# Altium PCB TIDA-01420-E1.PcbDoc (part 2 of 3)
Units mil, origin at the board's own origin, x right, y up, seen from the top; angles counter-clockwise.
Board outline 6575 x 7007.88 mil, 4 copper layers (Top Layer, GND, PWR, Bottom Layer), stack 79.834 mil thick; 326 components, 128 nets, 736 pads, 186 vias.
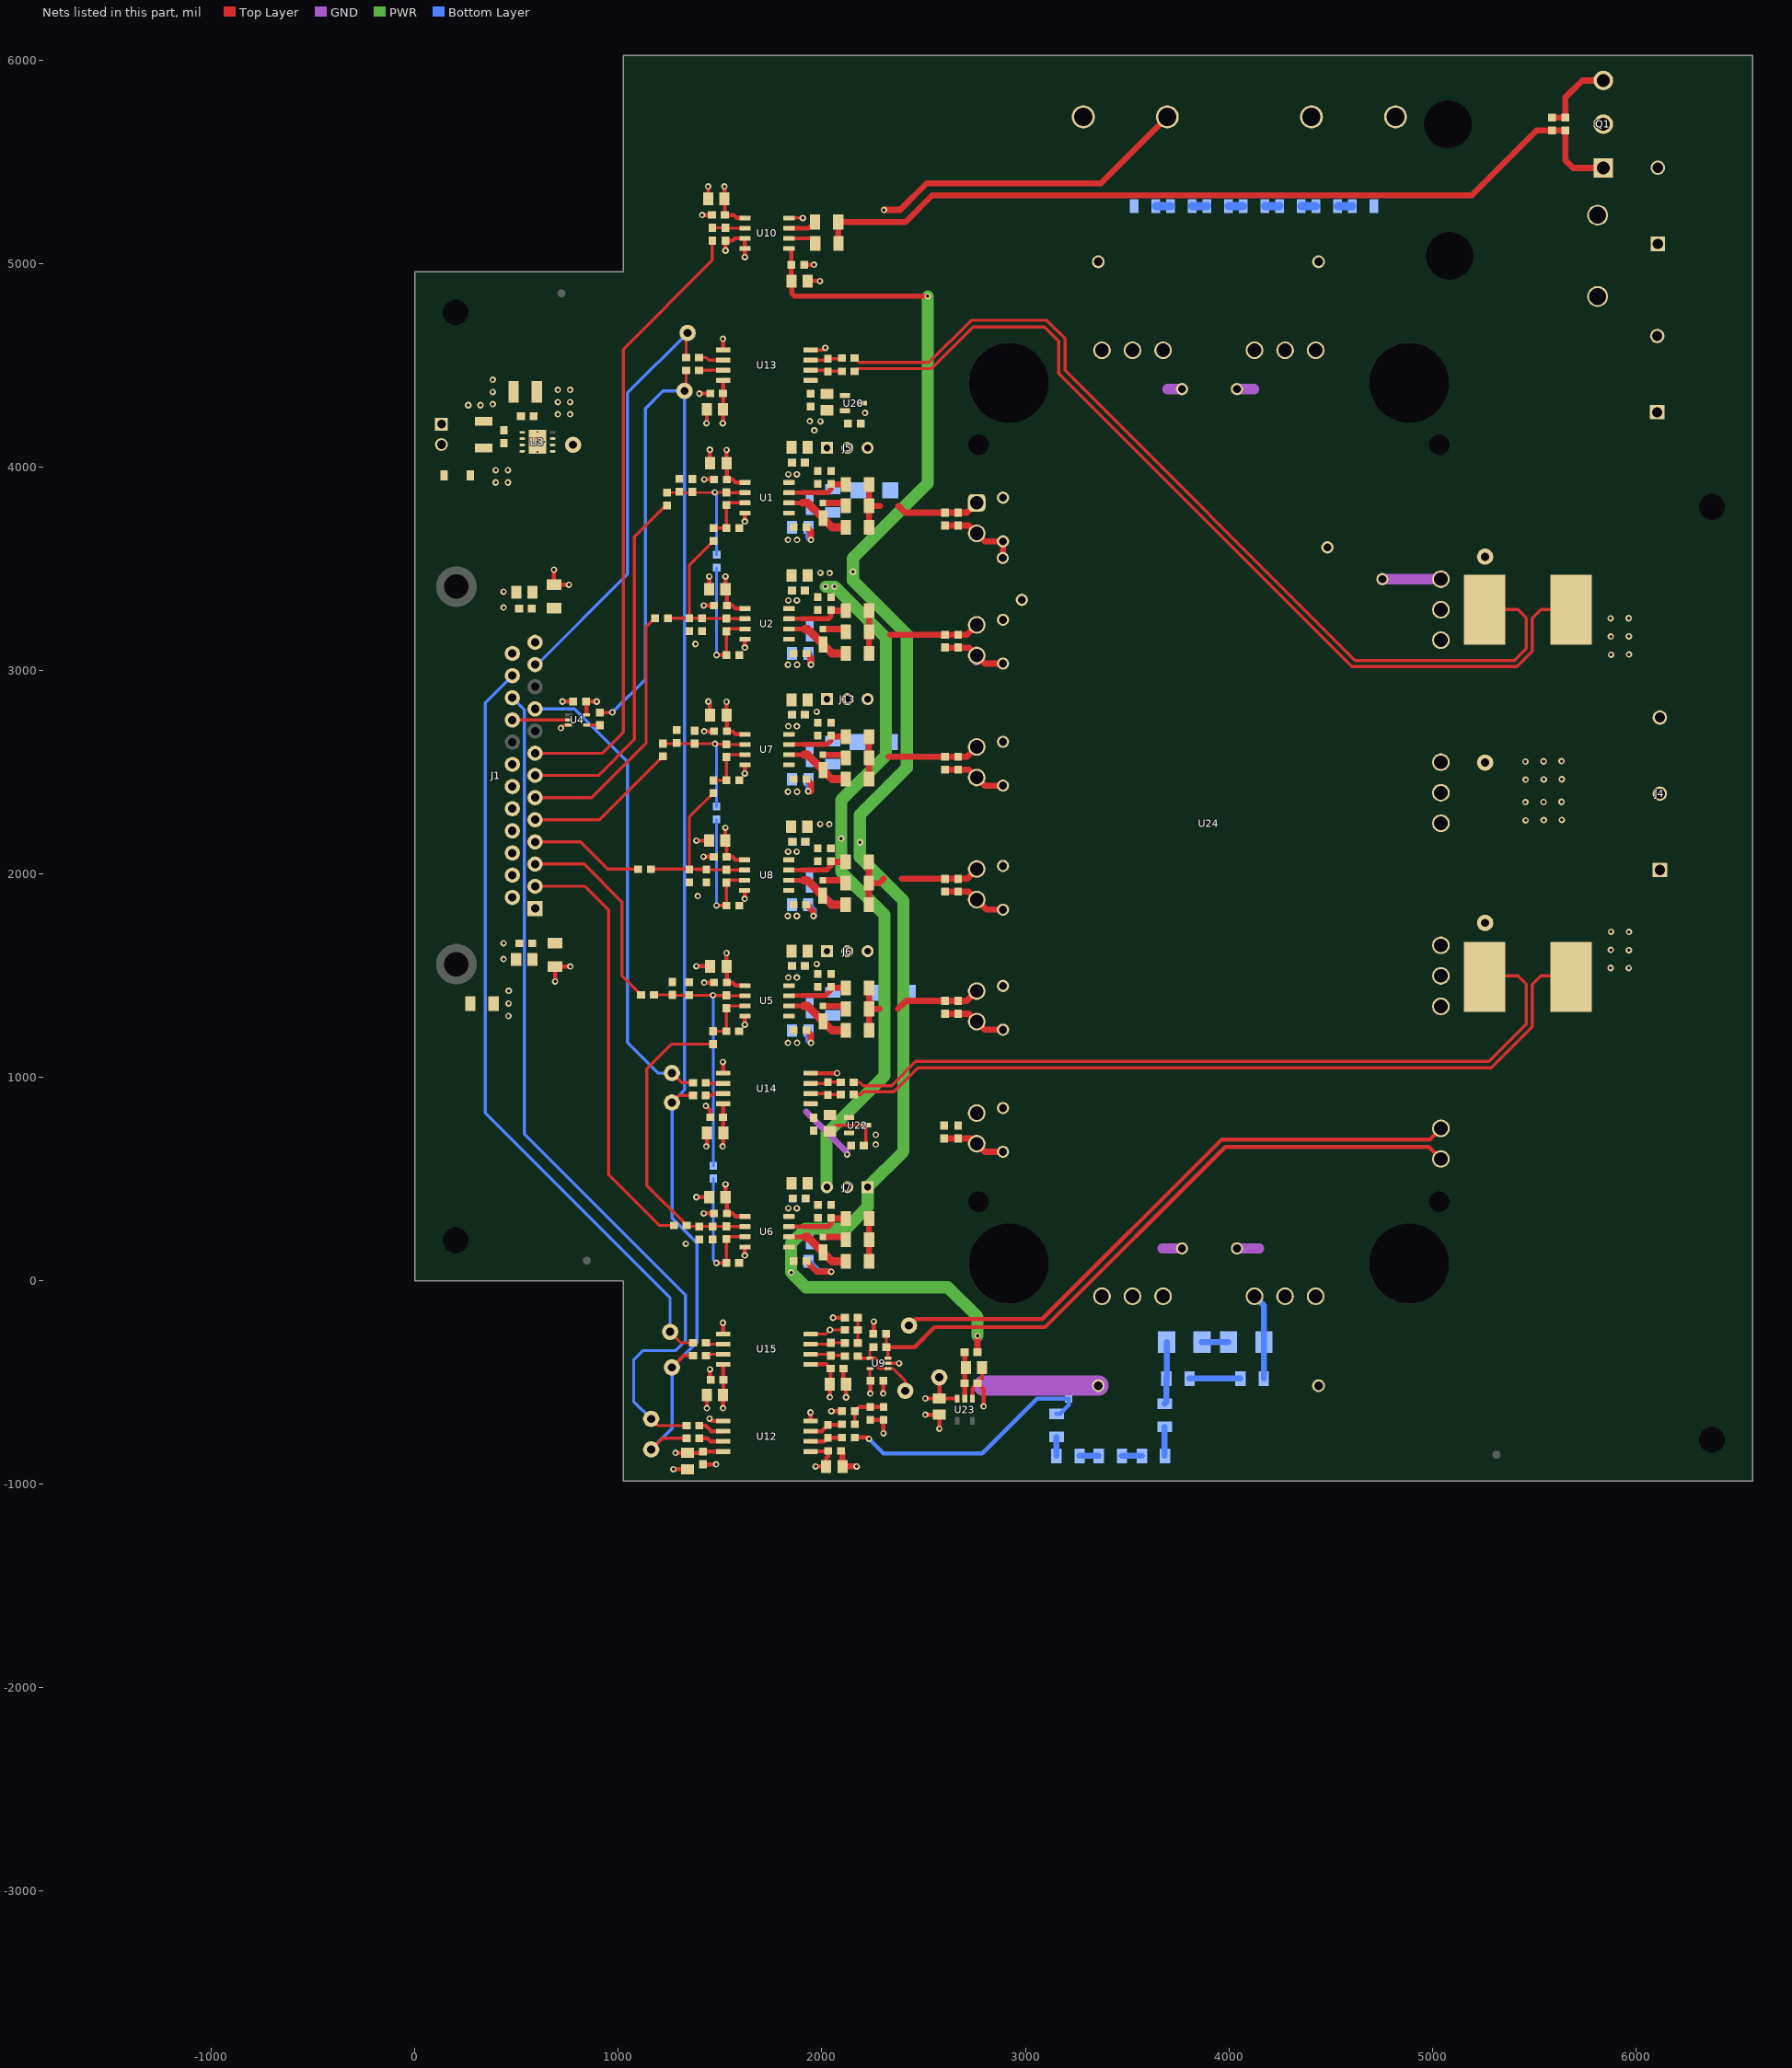
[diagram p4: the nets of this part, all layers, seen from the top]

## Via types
v1: diameter 32, hole 16, Top Layer to Bottom Layer, 181 vias
v2: diameter 19.68, hole 7.87, Top Layer to Bottom Layer, 5 vias

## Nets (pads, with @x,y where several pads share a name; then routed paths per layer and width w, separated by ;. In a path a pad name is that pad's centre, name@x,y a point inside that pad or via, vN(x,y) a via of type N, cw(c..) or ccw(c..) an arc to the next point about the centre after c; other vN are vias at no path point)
3V3: C6.1 C9.1 C11.1 C17.1 C19.1 C22.1 C24.1 C25.1 C27.1 C29.1 C30.1 C36.1 C38.1 C42.1 C44.1 C57.1 C58.2 C59.2 C61.2 C62.2 C63.2 C65.2 C66.2 C68.1 C70.2 TP4.1 U1.1 U2.1 U3.5 U3.6 U3.7 U3.9 U4.5 U5.1 U6.1 U7.1 U8.1 U10.1 U12.8 U13.8 U14.8 U15.8 | length 2691.7
  Top Layer w20: U4.5@843.29,2783.59 843.29,2845.2 C30.1@840.5,2848 v1(893,2848) ; v1(1280,-845) C58.2@1340,-845 1408.5,-845 C63.2@1415,-838.5 C63.2@1415,-838.5 U12.8@1515.17,-838.55 ; v1(1512.73,4216.45) 1514.73,4218.45 C59.2@1514.73,4284.45 1514.73,4361.95 C65.2@1514.23,4362.45 1515.17,4363.39 U13.8@1515.17,4426.58 ; v1@1514.16,663.13 1515.5,664.47 C62.2@1515.5,728 ; C62.2@1514.16,728 1514.16,795.55 1514.94,796.33 U14.8@1514.94,871 ; v1(1514.73,-625.55) C61.2@1514.73,-560.55 1516.23,-559.05 C70.2@1516.23,-485.55 1515.17,-484.49 U15.8@1515.17,-410.55 ; v1(1521.3,5380) C22.1@1521.3,5320 1522.8,5318.5 C11.1@1522.8,5240 1566.3,5240 1581.3,5225 U10.1@1621.73,5225 ; C44.1@1525.3,2165 v1(1525.3,2227.99) ; C29.1@1526.3,412 v1(1526.3,474.99) ; C9.1@1526.3,3400 v1(1526.3,3462.99) ; C44.1@1530.3,2165 1530.3,2160 1531.8,2158.5 C42.1@1531.8,2085 1560.3,2085 1575.3,2070 U8.1@1620.73,2070 ; C29.1@1531.3,412 1531.3,407 1532.8,405.5 C27.1@1532.8,332 1561.3,332 1576.3,317 U6.1@1621.73,317 ; C19.1@1531.3,1541.97 C19.1@1531.3,1546.97 ; v1(1531.3,1611.97) C19.1@1531.3,1546.97 ; C38.1@1531.3,2776.97 C38.1@1531.3,2781.97 ; v1(1531.3,2846.97) C38.1@1531.3,2781.97 ; C9.1@1531.3,3400 1531.3,3395 1532.8,3393.5 C6.1@1532.8,3320 1561.3,3320 1576.3,3305 U2.1@1621.73,3305 ; C57.1@1531.3,4015 C57.1@1531.3,4020 ; v1(1531.3,4085) C57.1@1531.3,4020 ; U5.1@1621.73,1451.97 1576.3,1451.97 1561.3,1466.97 C17.1@1532.8,1466.97 1532.8,1545.47 C19.1@1531.3,1546.97 ; U7.1@1621.73,2686.97 1576.3,2686.97 1561.3,2701.97 C36.1@1532.8,2701.97 1532.8,2780.47 C38.1@1531.3,2781.97 ; U1.1@1621.73,3925 1576.3,3925 1561.3,3940 C68.1@1532.8,3940 1532.8,4018.5 C57.1@1531.3,4020
  other v1: 1512.16,661.13 702,4260 762,4260 702,4320 762,4320 702,4380 762,4380
  other v2: 602,4075.79 568.54,4125 602,4125 635.46,4125 602,4174.21
3V3_VDC: C64.2 C67.2 C79.1 C82.2 C91.2 C95.1 R81.1 R90.2 R106.1 TP7.1 U9.5 U12.1 U15.1 U23.3 | length 1005.6
  Top Layer w15: C79.1@2235.71,-487.2 U9.5@2235.71,-430.59
  Top Layer w20: U12.1@1944.3,-838.55 1945.12,-837.73 2010.42,-837.73 ; U15.1@1944.3,-410.55 1945.12,-409.73 2022.42,-409.73 C91.2@2043.24,-430.55 2043.24,-503.76 C67.2@2039,-508 v1(2039,-571) ; v1(1969,-912) C64.2@2021,-912 2021,-871 2030.77,-861.23 C82.2@2030.77,-835.95 ; v1(2046.5,-639.99) 2047,-639.5 R81.1@2098.5,-639.5 ; v1(2054.73,-180.55) R90.2@2113.24,-180.55 ; C79.1@2235.71,-487.2 C79.1@2238.5,-490 v1(2238.5,-553) ; R106.1@2255.27,-257.95 v1(2255.27,-199.45) ; v1(2508.33,-577.68) C95.1@2577.33,-577.68 ; TP7.1@2577,-474 2577.33,-474.33 C95.1@2577.33,-577.68 ; TP7.1@2577.33,-460.95 TP7.1@2579.73,-458.55 ; U23.3@2664.93,-578.55 2664.06,-577.68 C95.1@2577.33,-577.68
5V0: C5.1 C14.1 D1.1 R1.1 R6.1 U3.2 U3.3 U3.4 | length 296.1
  Top Layer w20: R6.1@683,3422.09 756.91,3422.09 v1(757,3422.17) ; v1(683,3496.17) 683.09,3496.09 R6.1@683.09,3422.17 ; R1.1@688.91,1546 688.91,1472.09 v1(689,1472) ; R1.1@689,1545.91 762.91,1545.91 v1(763,1546)
  other v1: 397,3925 457,3925 397,3985 457,3985
BRAKE_IGBT_GATE: C78.1 Q1.1 R71.2 R94.2 R96.2 | length 4214
  Top Layer w30: R94.2@2080.44,5099.25 R71.2@2080.44,5205.25 2411.25,5205.25 2542,5336 5193.99,5336 5513,5655.01 R96.2@5589,5655.01 C78.1@5654,5655.01 5654,5510 5693,5471 Q1.1@5841,5471
GND: C1.1 C2.1 C5.2 C6.2 C7.2 C8.2 C9.2 C10.2 C11.2 C14.2 C17.2 C19.2 C22.2 C24.2 C25.2 C27.2 C29.2 C30.2 C36.2 C38.2 C42.2 C44.2 C57.2 C58.1 C59.1 C61.1 C62.1 C63.1 C65.1 C66.1 C68.2 C70.1 C162.2 C163.2 C164.2 C165.2 C166.2 C167.2 J1.14 J1.15 J1.16 J1.17 J1.18 J1.19 J1.20 J1.25 J2.1 R44.1 R162.1 R163.1 R164.1 R165.1 R166.1 R167.1 R168.1 R169.1 R170.1 R171.1 R172.1 R173.1 U1.4 U2.4 U3.1 U4.3 U5.4 U6.4 U7.4 U8.4 U10.3 U10.4 U12.5 U13.5 U14.5 U15.5 | length 2149.5
  Top Layer w15: v1(717,2718) 731.41,2732.41 U4.3@754.71,2732.41
  Top Layer w20: v1@460,1364 v1(460.09,1364.09) ; v1(725,2848) C30.2@777.5,2848 ; v1(1270,-925) 1279.72,-925 C58.1@1340,-925 ; v1(1383.31,412) C29.2@1446.3,412 ; v1(1383.31,1546.97) C19.2@1449.8,1546.97 ; v1(1383.31,2164) C44.2@1446.3,2164 ; v1(1397.73,4361.45) 1398.73,4362.45 C65.1@1451.24,4362.45 ; v1@1409.29,5240 v1(1411.3,5240) C11.2@1459.8,5240 ; C63.1@1414.05,-900.27 1415.55,-901.76 v1(1480.55,-901.76) ; v1(1418.29,2085) C42.2@1468.8,2085 ; v1(1419.29,332) C27.2@1469.8,332 ; v1@1419.29,1466.97 v1(1421.3,1466.97) C17.2@1469.8,1466.97 ; v1@1419.29,2701.97 v1(1421.3,2701.97) C36.2@1469.8,2701.97 ; v1(1419.29,3320) C6.2@1469.8,3320 ; v1@1419.29,3940 v1(1421.3,3940) C68.2@1469.8,3940 ; v1(1429.77,860.55) 1451.01,839.31 C66.1@1451.01,804 ; v1(1432.73,4216.45) 1434.73,4218.45 C59.1@1434.73,4284.45 ; v1@1434.16,663.13 1435.5,664.47 C62.1@1435.5,728 ; C62.1@1434.16,728 C62.1@1434.16,729.13 ; v1(1434.73,-625.55) C61.1@1434.73,-560.55 C61.1@1436.23,-559.05 ; C22.2@1441.3,5320 v1(1441.3,5380) ; v1(1442.3,2848) v1@1445.26,2848 ; C9.2@1446.3,3400 v1(1446.3,3462.99) ; v1(1448,-677) 1459.55,-688.55 U12.5@1515.17,-688.55 ; v1(1449.3,4086) 1449.8,4086.5 C57.2@1449.8,4020 ; C38.2@1449.8,2781.97 v1@1449.8,2848.47 ; v1(1450,-435) 1450,-482.31 C70.1@1453.24,-485.55 C70.1@1454.73,-487.05 ; v1(1513.09,1076.25) 1514.59,1074.76 U14.5@1514.59,1021.25 ; v1(1513.67,-205.55) 1515.17,-207.05 U15.5@1515.17,-260.55 ; v1(1513.67,4631.58) 1515.17,4630.08 U13.5@1515.17,4576.58 ; v1@1526.3,5062.99 v1(1526.3,5065) C10.2@1526.3,5113.5 1559.8,5113.5 1571.3,5125 U10.3@1621.73,5125 U10.4@1621.73,5075 1621.73,5033.46 v1(1621.3,5033.03) ; v1(1620.3,1878.03) 1620.73,1878.46 U8.4@1620.73,1920 ; v1(1621.3,125.03) 1621.73,125.46 U6.4@1621.73,167 ; v1(1621.3,1260) 1621.73,1260.43 U5.4@1621.73,1301.97 ; v1(1621.3,2495) 1621.73,2495.43 U7.4@1621.73,2536.97 ; v1(1621.3,3113.03) 1621.73,3113.46 U2.4@1621.73,3155 ; v1(1621.3,3733.03) 1621.73,3733.46 U1.4@1621.73,3775
  other v1: 1331,183 1432.16,661.13 459.17,1302.17 461,1426 435,1582 435,1660 1390,1892 1379,3131 435,3310 435,3388 262,4305 322,4305 382.77,4309.98 382.77,4369.98 382.77,4429.98
GND_UT: C18.1 C20.1 C21.1 C23.2 C26.2 C74.2 C85.1 C89.1 J6.2 R14.2 R16.2 R112.1 TP18.1 U14.4 U22.3 U24.10 | length 863.2
  Top Layer w15: C85.1@2039.77,735.55 2069.77,765.55 U22.3@2216.11,765.55 C21.1@2216.11,675.39
  Top Layer w20: U14.4@1944.07,1021 2074.22,1021 v1(2074.77,1021.55)
  Top Layer w30: C23.2@1924.5,1231.97 1946,1210.47 v1@1946,1170.97 ; R112.1@2605,1313.5 C74.2@2670,1313.5 2722.2,1313.5 U24.10@2761.14,1274.57 2800.71,1235 TP18.1@2890,1235
  Bottom Layer w30: C26.2@1934,1230.97 1934,1181.97 v1(1946,1169.97)
  other v1: 2264.77,670.55 2264.77,718.55 1975,1558
GND_VT: C37.1 C39.1 C40.2 C41.2 C73.2 J13.2 R28.2 R30.2 R32.1 TP16.1 U24.6 | length 446.8
  Top Layer w30: C40.2@1924.5,2466.97 1946,2445.47 v1@1946,2405.97 ; R32.1@2605,2513.5 C73.2@2670,2513.5 2722.2,2513.5 U24.6@2761.14,2474.57 2800.71,2435 TP16.1@2890,2435
  Bottom Layer w30: v1(1933,2407) 1933,2415.97 1934,2416.97 C41.2@1934,2465.97
  other v1: 1975,2798
GND_WT: C3.2 C4.2 C15.1 C16.1 C71.1 C72.2 C80.1 C87.1 J5.2 R2.2 R4.2 R20.1 TP13.1 TP30.1 U13.4 U20.3 U24.2 | length 611.8
  Top Layer w15: U13.4@1944.3,4576.58 2006.58,4576.58 v1(2017,4587)
  Top Layer w30: C3.2@1924.5,3705 1946,3683.5 v1@1946,3644 ; R20.1@2605,3713.5 C72.2@2670,3713.5 2722.2,3713.5 U24.2@2761.14,3674.57 2800.71,3635 TP13.1@2890,3635 2890,3555 TP30.1@2889,3554
  Bottom Layer w30: C4.2@1934,3704 1934,3655 v1(1946,3643)
  other v1: 1963,4181 1993,4225 1941,4226 2212,4267
IN+_B_U: C105.1 C163.1 R144.1 R151.1 R163.2 U6.2 | length 1512.9
  Top Layer w15: R144.1@1335.5,268.5 C105.1@1531.3,268.5 1532.8,267 U6.2@1621.73,267 ; R144.1@1335.5,273 1140,468.5 1140,1042 1262.5,1164.5 R151.1@1465.37,1164.5
IN+_B_V: C103.1 C167.1 R141.1 R159.1 R167.2 U8.2 | length 937.6
  Top Layer w15: R141.1@1159.32,2024.1 R167.2@1348.37,2024.1 ; R167.2@1348.82,2022.59 1348.37,2023.05 R167.2@1348.37,2024.1 ; 1381.87,2021.5 C103.1@1530.3,2021.5 1531.8,2020 U8.2@1620.73,2020 ; C167.1@1432.82,2022.58 1431.31,2024.1 R167.2@1348.37,2024.1 ; R159.1@1466.37,2397.5 1348.37,2279.5 R167.2@1348.37,2024.1
IN+_B_W: C101.1 C165.1 R139.1 R155.1 R165.2 U2.2 | length 807.5
  Top Layer w15: R139.1@1243.5,3257 1243.8,3257.31 R165.2@1348.3,3257.31 ; 1386.69,3257.31 R165.2@1348.3,3257.31 ; 1387.5,3256.5 C101.1@1531.3,3256.5 1532.8,3255 U2.2@1621.73,3255 ; R155.1@1467,3637.5 1349,3519.5 1349,3258.01 R165.2@1348.3,3257.31
IN+_T_U: C106.1 C162.1 R143.1 R150.2 R162.2 U5.2 | length 1292.6
  Top Layer w15: R143.1@1174.5,1406 1175,1406.5 C162.1@1265,1406.5 1267.5,1404 v1(1465,1404) ; v1@1472,1405 1467.83,1405 1466.3,1403.47 C106.1@1531.3,1403.47 1532.8,1401.97 U5.2@1621.73,1401.97
  Bottom Layer w15: R150.2@1466,566.5 v1@1466,1399 ; v1@1472,1399 v1@1472,1405
IN+_T_V: C104.1 C166.1 R142.1 R158.1 R166.2 U7.2 | length 722.4
  Top Layer w15: R142.1@1219,2641.5 v1@1471.97,2641.5 ; v1@1466.3,2638.47 C104.1@1531.3,2638.47 1532.8,2636.97 U7.2@1621.73,2636.97
  Bottom Layer w15: v1(1475,2641) 1482,2634 R158.1@1482,2332.5 R158.1@1482,2330.5
IN+_T_W: C102.1 C164.1 R140.1 R154.1 R164.2 U1.2 | length 700.4
  Top Layer w12: R140.1@1239,3874.5 v1@1472,3874.5
  Top Layer w15: v1@1466.3,3876.5 v1(1474,3876.5) C102.1@1531.3,3876.5 1532.8,3875 U1.2@1621.73,3875
  Bottom Layer w12: v1(1474,3876.5) v1@1482,3868.5
  Bottom Layer w15: R154.1@1482,3568.5 v1@1482,3868.5
IN-_B_U: C105.2 R150.1 R169.2 U6.3 | length 682.8
  Top Layer w15: v1(1481.5,88.5) R169.2@1530.3,88.5 1530.3,204.5 C105.2@1531.3,205.5 1542.8,217 U6.3@1621.73,217
  Bottom Layer w15: R150.1@1466,503.5 1466,104 v1(1481.5,88.5)
IN-_B_V: C103.2 R158.2 R173.2 U8.3 | length 679.3
  Top Layer w15: v1(1482.2,1845.5) R173.2@1531,1845.5 1531,1957.8 C103.2@1530.3,1958.5 1541.8,1970 U8.3@1620.73,1970
  Bottom Layer w15: v1(1482.2,1845.5) R158.2@1482.2,2267.5
IN-_B_W: C101.2 R154.2 R171.2 U2.3 | length 690.2
  Top Layer w15: v1(1482.2,3076.5) R171.2@1531,3076.5 1531,3193.2 C101.2@1531.3,3193.5 1542.8,3205 U2.3@1621.73,3205
  Bottom Layer w15: R154.2@1482,3505.5 1482.2,3505.3 v1(1482.2,3076.5)
IN-_T_U: C106.2 R151.2 R168.2 U5.3 | length 273.5
  Top Layer w15: R151.2@1465.37,1227.5 R168.2@1530.3,1227.5 1530.3,1339.47 C106.2@1531.3,1340.47 1542.8,1351.97 U5.3@1621.73,1351.97
IN-_T_V: C104.2 R159.2 R172.2 U7.3 | length 274.9
  Top Layer w15: R159.2@1466.37,2460.5 1531,2460.5 R172.2@1531.3,2460.8 C104.2@1531.3,2575.47 1542.8,2586.97 U7.3@1621.73,2586.97
IN-_T_W: C102.2 R155.2 R170.2 U1.3 | length 272.3
  Top Layer w15: R155.2@1467,3700.5 R170.2@1531,3700.5 1531.3,3700.8 C102.2@1531.3,3813.5 1542.8,3825 U1.3@1621.73,3825
MCLK: R7.2 R46.2 R52.2 R55.2 R58.2 TP2.1 TP6.1 TP11.1 TP15.1 | length 7770.9
  Top Layer w15: v1@969.5,2794.5 v1(970,2795) ; TP6.1@1325,4375 1333.01,4383.01 R52.2@1333.01,4476
  Top Layer w16: R7.2@909,2794.5 v1@969.5,2794.5 ; TP2.1@1161,-828 1216,-773 R55.2@1335.01,-773 ; TP15.1@1263,-425 1321,-367 R58.2@1367.01,-367 ; TP11.1@1263,877 1297.55,911.55 R46.2@1366.46,911.55
  Bottom Layer w16: v1(970,2795) 1132,2957 1132,4288 1219,4375 TP6.1@1325,4375 1325,939 TP11.1@1263,877 1263,310 1387,186 1387,-301 TP15.1@1263,-425 1263,-726 TP2.1@1161,-828
MDATA_TMP: J1.24 R59.2 TP3.1 | length 3792.7
  Top Layer w15: TP3.1@1254,-250 1308,-304 R59.2@1367.01,-304
  Bottom Layer w15: J1.24@478.5,2975.5 345,2842 345,826 1254,-83 TP3.1@1254,-250
MDATA_U: J1.10 R47.2 TP10.1 | length 2345.8
  Top Layer w15: TP10.1@1263,1022 1310.45,974.55 R47.2@1366.46,974.55
  Bottom Layer w15: J1.10@590.5,2812 785,2812 1045,2552 1045,1171.32 1194.32,1022 TP10.1@1263,1022
MDATA_VDC: J1.23 R56.2 TP1.1 | length 4323.6
  Top Layer w15: TP1.1@1161,-678 1194,-711 R56.2@1335.01,-711
  Bottom Layer w15: J1.23@478.5,2866.5 537.5,2807.5 537.5,2790.05 538,2789.55 538,2725.45 537.5,2724.95 537.5,2681.05 538,2680.55 538,2616.45 537.5,2615.95 537.5,2572.05 538,2571.55 538,2507.45 537.5,2506.95 537.5,2463.05 538,2462.55 538,2398.45 537.5,2397.95 537.5,2354.05 538,2353.55 538,2289.45 537.5,2288.95 537.5,2245.05 538,2244.55 538,2180.45 537.5,2179.95 537.5,2136.05 538,2135.55 538,2071.45 537.5,2070.95 537.5,2027.05 538,2026.55 538,1962.45 537.5,1961.95 537.5,1918.05 538,1917.55 538,1875.42 537.5,1874.92 537.5,1787.08 538,1786.58 538,722 1330,-70 1330,-294 1282,-342 1122,-342 1075,-389 1075,-592 TP1.1@1161,-678
MDATA_W: J1.12 R53.2 TP5.1 | length 2069.8
  Top Layer w15: R53.2@1333.01,4532 R53.2@1333.01,4539 1333.01,4653.01 TP5.1@1335,4655
  Bottom Layer w15: J1.12@590.5,3030 600,3030 1045,3475 1045,4365 TP5.1@1340,4660
NetC1_2: C1.2 C2.2 J1.1 R1.2
NetC7_1: C7.1 C8.1 J1.13 R6.2
NetC10_1: C10.1 R8.1 U10.2 | length 161.1
  Top Layer w15: R8.1@1461.3,5176.5 C10.1@1526.3,5176.5 1527.8,5175 U10.2@1621.73,5175
NetC12_2: C12.2 C13.2 R10.1 R102.2 U2.8
  other v1: 1835,3345 1877,3345
NetC15_2: C15.2 C16.2 R4.1 R100.2 U1.8
  other v1: 1835,3965 1877,3965
NetC18_2: C18.2 C20.2 R16.1 R99.2 U5.8
  other v1: 1835,1491.97 1877,1491.97
NetC28_2: C28.2 C31.2 R24.1 R101.2 U6.8
  other v1: 1835,357 1877,357
NetC37_2: C37.2 C39.2 R30.1 R103.2 U7.8
  other v1: 1835,2726.97 1877,2726.97
NetC43_2: C43.2 C45.2 R36.1 R105.2 U8.8
  other v1: 1834,2110 1876,2110
NetC80_2: C80.2 C87.2 U13.1 U20.1
NetC81_1: C81.1 R83.2 U12.2 | length 162.1
  Top Layer w20: U12.2@1944.3,-788.55 2012.44,-788.55 C81.1@2030,-770.99 2097.01,-770.99 R83.2@2098.5,-769.5
NetC81_2: C81.2 R82.2 U12.3 | length 167.5
  Top Layer w20: U12.3@1944.3,-738.55 1998.6,-738.55 2003.84,-733.31 C81.2@2029.15,-708 ; C81.2@2030,-708 2095,-708 R82.2@2098.5,-704.5
NetC83_1: C83.1 R86.2 U13.2 | length 157.2
  Top Layer w15: U13.2@1944.3,4476.58 2023.24,4476.58 C83.1@2029.73,4470.08 2031.23,4471.58 R86.2@2098.24,4471.58
NetC83_2: C83.2 R85.2 U13.3 | length 153.1
  Top Layer w15: U13.3@1944.3,4526.58 C83.2@2023.24,4526.58 ; C83.2@2029.73,4533.07 R85.2@2094.73,4533.07
  Top Layer w20: C83.2@2023.24,4526.58 C83.2@2029.73,4533.07
NetC84_1: C84.1 R80.2 U14.2 | length 157.2
  Top Layer w15: U14.2@1943.72,921.25 2022.66,921.25 2029.16,914.76 2030.65,916.25 R80.2@2097.66,916.25
NetC84_2: C84.2 R79.2 U14.3 | length 153.1
  Top Layer w15: U14.3@1943.72,971.25 C84.2@2022.66,971.25 ; C84.2@2029.16,977.75 R79.2@2094.16,977.75
  Top Layer w20: C84.2@2022.66,971.25 C84.2@2029.16,977.75
NetC85_2: C85.2 C89.2 U14.1 U22.1
NetC92_1: C92.1 R93.2 U15.2 | length 172.2
  Top Layer w15: U15.2@1944.3,-360.55 2038.24,-360.55 C92.1@2044.73,-367.05 2046.23,-365.55 R93.2@2113.24,-365.55
NetC92_2: C92.2 R92.2 U15.3 | length 172.2
  Top Layer w15: U15.3@1944.3,-310.55 2038.24,-310.55 C92.2@2044.73,-304.05 2111.74,-304.05 R92.2@2113.24,-305.55
NetC94_2: C94.2 R81.2 R82.1 R107.2 | length 213.8
  Top Layer w15: R82.1@2161.5,-704.5 R81.2@2161.5,-639.5
  Top Layer w20: R81.2@2162.82,-640.82 2183.64,-620 R107.2@2238,-620 C94.2@2303,-620
NetC96_1: C96.1 C97.1 R110.2 U23.2 | length 232.6
  Top Layer w25: R110.2@2701.84,-350.68 2701.84,-421.19 C96.1@2707.33,-426.68 2701.84,-432.18 C97.1@2701.84,-502.68 2702.33,-503.18 U23.2@2702.33,-578.55
NetD1_2: D1.2 J2.2
NetD2_1: D2.1 R13.1 U2.6 | length 313.1
  Top Layer w22: U2.6@1854.57,3205 1917,3205
  Top Layer w40: 1917,3205 1929.41,3205 D2.1@2005,3129.41 2049.41,3085 R13.1@2117.91,3085
NetD2_2: D2.2 R11.1 | length 98.7
  Top Layer w30: D2.2@2005,3204.21 R11.1@2103.7,3204.21
NetD3_1: D3.1 R19.1 U1.6 | length 313.1
  Top Layer w22: U1.6@1854.57,3825 1906,3825
  Top Layer w40: 1906,3825 1929.41,3825 D3.1@2005,3749.41 2049.41,3705 R19.1@2117.91,3705
NetD3_2: D3.2 R17.1 | length 98.7
  Top Layer w30: D3.2@2005,3824.21 R17.1@2103.7,3824.21
NetD4_1: D4.1 R21.1 U5.6 | length 313.1
  Top Layer w22: U5.6@1854.57,1351.97 1912,1351.97
  Top Layer w40: 1912,1351.97 1929.41,1351.97 D4.1@2005,1276.38 2049.41,1231.97 R21.1@2117.91,1231.97
NetD4_2: D4.2 R18.1 | length 118.8
  Top Layer w30: D4.2@2005,1351.18 2103.7,1351.18 R18.1@2117.91,1336.97
NetD5_1: D5.1 R27.1 U6.6 | length 313.1
  Top Layer w22: U6.6@1854.57,217 1917,217
  Top Layer w40: 1917,217 1929.41,217 D5.1@2005,141.41 2049.41,97 R27.1@2117.91,97
NetD5_2: D5.2 R25.1 | length 98.7
  Top Layer w30: D5.2@2005,216.21 R25.1@2103.7,216.21
NetD6_1: D6.1 R33.1 U7.6 | length 313.1
  Top Layer w22: U7.6@1854.57,2586.97 1914,2586.97
  Top Layer w40: 1914,2586.97 1929.41,2586.97 D6.1@2005,2511.38 2049.41,2466.97 R33.1@2117.91,2466.97
NetD6_2: D6.2 R31.1 | length 98.7
  Top Layer w30: D6.2@2005,2586.18 R31.1@2103.7,2586.18
NetD7_1: D7.1 R39.1 U8.6 | length 313.1
  Top Layer w22: U8.6@1853.57,1970 1912,1970
  Top Layer w40: 1912,1970 1928.41,1970 D7.1@2004,1894.41 2048.41,1850 R39.1@2116.91,1850
NetD7_2: D7.2 R37.1 | length 98.7
  Top Layer w30: D7.2@2004,1969.21 R37.1@2102.7,1969.21
NetD9_2: D9.2 J3.1 Q1.2
NetD10_2: D10.2 D11.1 | length 130
  Bottom Layer w30: D11.1@3868.75,-300.55 D10.2@3998.73,-300.55
NetD11_2: D11.2 R108.1 R122.2 | length 306.4
  Bottom Layer w30: R122.2@3685,-602.91 3692.91,-595 R108.1@3692.91,-480 3694.73,-478.18 D11.2@3694.73,-300.55
NetD12_1: D12.1 R41.2
NetD13_1: D13.1 R42.2
NetD14_1: D14.1 R43.2
NetJ1_22: J1.22 U4.2 | length 276.4
  Top Layer w15: J1.22@478.5,2757.5 754.21,2757.5 U4.2@754.71,2758
NETJ1_26: R44.2
NetJ4_2: J4.2 TP31.1 U24.24 U24.25 U24.26
  other v1: 5459,2264 5548,2265 5637,2266 5458,2353 5547,2354 5636,2355 5459,2464 5548,2465 5637,2466 5458,2553 5547,2554 5636,2555
NetR2_1: R2.1 R3.1 U1.7 | length 298.3
  Top Layer w20: U1.7@1854.57,3875 1905,3875
  Top Layer w25: 1905,3875 2028,3875 2045,3892 R2.1@2045,3918.5
  Top Layer w30: R2.1@2045,3918.5 2048.5,3915 R3.1@2117.91,3915
NetR5_1: R5.1 R9.1 U2.7 | length 300.7
  Top Layer w20: U2.7@1854.57,3255 1903,3255
  Top Layer w25: 1903,3255 2003.87,3255 2032,3255 2045,3268 R5.1@2045,3298.5
  Top Layer w30: R5.1@2045,3298.5 2048.5,3295 R9.1@2117.91,3295
NetR7_1: R7.1 U4.4 | length 66.1
  Top Layer w15: U4.4@843.29,2732.41 908.09,2732.41 R7.1@909,2731.5
NetR14_1: R14.1 R15.1 U5.7 | length 285.9
  Top Layer w20: U5.7@1854.57,1401.97 1903,1401.97
  Top Layer w25: 1903,1401.97 2016.97,1401.97 2045,1430 R14.1@2045,1445.47
  Top Layer w30: R14.1@2049.5,1440.97 R15.1@2117.91,1440.97
NetR22_1: R22.1 R23.1 U6.7 | length 300.1
  Top Layer w20: U6.7@1854.57,267 1914,267
  Top Layer w25: 1914,267 2031,267 2045,281 R22.1@2045,310.5
  Top Layer w30: R22.1@2045,310.5 2048.5,307 R23.1@2117.91,307
NetR28_1: R28.1 R29.1 U7.7 | length 297.6
  Top Layer w20: U7.7@1854.57,2636.97 1908,2636.97
  Top Layer w25: 1908,2636.97 2025.97,2636.97 2045,2656 R28.1@2045,2680.47
  Top Layer w30: R28.1@2045,2680.47 2049.5,2675.97 R29.1@2117.91,2675.97
NetR34_1: R34.1 R35.1 U8.7 | length 296.1
  Top Layer w20: U8.7@1853.57,2020 1903,2020
  Top Layer w25: 1903,2020 2023.18,2020 2044,2040.82 R34.1@2044,2063.5
  Top Layer w30: R34.1@2044,2063.5 2047.5,2060 R35.1@2116.91,2060
NetR40_1: R40.1 R106.2 U9.3 U24.19 | length 3281.4
  Top Layer w15: R106.2@2315.95,-259.73 2316.5,-260.28 R40.1@2316.5,-325 2324.29,-332.8 U9.3@2324.29,-379.41
  Top Layer w20: R40.1@2316.5,-325 2455.5,-325 2553.5,-227 3097,-227 3983,659 4983.4,659 U24.19@5042.64,599.76
NetR40_2: R40.2 R93.1 TP37.1 U9.1 U9.4 | length 415.5
  Top Layer w15: R93.1@2176.5,-370 2185.91,-379.41 U9.4@2235.71,-379.41 ; R40.2@2253.5,-325 2235.71,-342.8 U9.4@2235.71,-379.41 ; TP37.1@2410,-540 2410,-490 2350.59,-430.59 U9.1@2324.29,-430.59 2280.59,-430.59 2275,-425 2275,-390 2264.41,-379.41 U9.4@2235.71,-379.41
NetR45_2: R45.2 R48.1 | length 72.2
  Bottom Layer w40: R48.1@4534.65,5283.69 R45.2@4606.85,5283.69
NetR46_1: R46.1 U14.7 | length 89.4
  Top Layer w15: R46.1@1429.45,911.55 1457.55,911.55 1467,921 U14.7@1514.94,921
NetR47_1: R47.1 U14.6 | length 87
  Top Layer w15: R47.1@1429.45,974.55 1433,971 U14.6@1514.94,971
NetR48_2: R48.2 R49.1 | length 72.2
  Bottom Layer w40: R49.1@4356.15,5283.69 R48.2@4428.35,5283.69
NetR49_2: R49.2 R50.1 | length 72.2
  Bottom Layer w40: R50.1@4177.65,5283.69 R49.2@4249.85,5283.69
NetR50_2: R50.2 R57.2 | length 72.2
  Bottom Layer w40: R57.2@3999.15,5283.69 R50.2@4071.35,5283.69
NetR51_2: R51.2 R54.1 | length 72.2
  Bottom Layer w40: R51.2@3642.15,5283.69 R54.1@3714.35,5283.69
NetR52_1: R52.1 U13.7 | length 122.3
  Top Layer w15: R52.1@1396,4469 1403.58,4476.58 U13.7@1515.17,4476.58
NetR53_1: R53.1 U13.6 | length 124.3
  Top Layer w15: R53.1@1396,4539 1432,4539 1444.42,4526.58 U13.6@1515.17,4526.58
NetR54_2: R54.2 R57.1 | length 72.2
  Bottom Layer w40: R54.2@3820.65,5283.69 R57.1@3892.85,5283.69
NetR55_1: R55.1 U12.7 | length 123.6
  Top Layer w20: R55.1@1398,-773 1437,-773 1452.55,-788.55 U12.7@1515.17,-788.55
NetR56_1: R56.1 U12.6 | length 128.6
  Top Layer w20: R56.1@1398,-711 1429.45,-711 1457,-738.55 U12.6@1515.17,-738.55
NetR58_1: R58.1 U15.7 | length 91.3
  Top Layer w15: R58.1@1426.5,-367 1432.95,-360.55 U15.7@1515.17,-360.55
NetR59_1: R59.1 U15.6 | length 90.5
  Top Layer w15: R59.1@1426.5,-315 1430.95,-310.55 U15.6@1515.17,-310.55
NetR71_1: R71.1 U10.7 | length 140.5
  Top Layer w22: U10.7@1838.27,5175 1936.02,5175 R71.1@1966.27,5205.25
NetR83_1: R83.1 R109.2 R129.1 | length 1304.8
  Top Layer w20: R83.1@2161.5,-769.5 2224.5,-769.5 v1(2231,-776)
  Bottom Layer w20: v1(2231,-776) 2303,-848 2789,-848 3058,-579 R109.2@3213,-579 3213,-611 3171.09,-652.91 R129.1@3153,-652.91
NetR90_1: R90.1 R91.2 R92.1 | length 125
  Top Layer w15: R92.1@2176.23,-305.55 R91.2@2176.23,-240.55 R90.1@2176.23,-180.55
NetR94_1: R94.1 U10.6 | length 150.5
  Top Layer w20: U10.6@1838.27,5125 1960,5125 1967.27,5117.73 R94.1@1967.27,5099.25
NetR98_1: R98.1 R108.2 | length 250.8
  Bottom Layer w30: R108.2@3807.09,-480 R98.1@4057.91,-480
NetR122_1: R122.1 R125.2 | length 140.8
  Bottom Layer w30: R125.2@3685,-857.91 R122.1@3685,-717.09
NetR125_1: R125.1 R127.2 | length 97.9
  Bottom Layer w30: R127.2@3475,-860 R125.1@3572.91,-860
NetR127_1: R127.1 R128.2 | length 93.7
  Bottom Layer w30: R128.2@3267.09,-860 R127.1@3360.83,-860
NetR128_1: R128.1 R129.2 | length 92.9
  Bottom Layer w30: R128.1@3152.91,-860 3153,-859.91 R129.2@3153,-767.09
PWM_BRAKE+: J1.8 R8.2 | length 3074.4
  Top Layer w15: J1.8@590.5,2594 922,2594 1024,2696 1024,4579 1461.3,5016.3 R8.2@1461.3,5113.5
PWM_UB+: J1.2 R144.2 | length 2134.6
  Top Layer w15: J1.2@590.5,1940 835,1940 952.2,1822.8 952.2,521.8 1201,273 R144.2@1272.5,273
PWM_UT+: J1.3 R143.2 | length 999.7
  Top Layer w15: J1.3@590.5,2049 831,2049 1018,1862 1018,1499.5 R143.2@1111.5,1406
PWM_VB+: J1.4 R141.2 | length 561.3
  Top Layer w15: J1.4@590.5,2158 813,2158 946.9,2024.1 R141.2@1096.33,2024.1
PWM_VT+: J1.5 R142.2 | length 757.5
  Top Layer w15: J1.5@590.5,2267 907.5,2267 R142.2@1219,2578.5
PWM_WB+: J1.6 R139.2 | length 1290.7
  Top Layer w15: J1.6@590.5,2376 869,2376 1136,2643 1136,3214.5 1135.5,3215 1177.5,3257 R139.2@1180.5,3257
PWM_WT+: J1.7 R140.2 | length 1776.7
  Top Layer w15: J1.7@590.5,2485 901,2485 1078,2662 1078,3658 R140.2@1233.5,3813.5
U_BOT: C75.1 R12.2 R23.2 R25.2 R27.2 TP19.1 U24.11 | length 210
  Top Layer w30: R27.2@2232.09,97 R25.2@2232.09,202 R23.2@2232.09,307
U_PHASE: J4.1 R80.1 R120.2 | length 3890.6
  Top Layer w15: R80.1@2156,916 2192,916 2206,930 2355,930 2472,1047 5289.43,1047 5492,1249.57 5492,1458 5534,1500 R120.2@5682.6,1500
  other v1: 5965.55,1537.45 5876.55,1538.45 5966.55,1626.45 5877.55,1627.45 5967.55,1715.45 5878.55,1716.45
U_PHASE_REF: R79.1 R120.1 TP32.1 U24.21 U24.22 U24.23 | length 3865
  Top Layer w15: R79.1@2156,976 2187,976 2203,960 2342.57,960 2461.57,1079 5279,1079 5462,1262 5462,1459 5421,1500 R120.1@5257.4,1500
  Top Layer w50: R120.1@5257.4,1495 R120.1@5257.4,1500 ; TP32.1@5257.4,1757.4 TP32.1@5260,1760
U_TOP: C74.1 R15.2 R18.2 R21.2 R112.2 TP17.1 U24.9 | length 685.5
  Top Layer w30: R21.2@2232.09,1231.97 R18.2@2232.09,1336.97 ; R15.2@2232.09,1441.97 R15.2@2232.09,1440.97 R18.2@2232.09,1336.97 ; 2283.97,1336.97 R18.2@2232.09,1336.97 ; 2373.97,1336.97 2413.5,1376.5 R112.2@2605,1376.5 C74.1@2670,1376.5 2712.68,1376.5 U24.9@2761.14,1424.96
V_BOT: C76.1 R35.2 R37.2 R38.2 R39.2 TP21.1 U24.7 | length 679
  Top Layer w30: R39.2@2231.09,1850 R37.2@2231.09,1955 ; R35.2@2231.09,2060 R37.2@2231.09,1955 ; 2303,1976.5 2281.5,1955 R37.2@2231.09,1955 ; 2393,1976.5 R38.2@2605,1976.5 C76.1@2670,1976.5 2712.68,1976.5 U24.7@2761.14,2024.96
V_TOP: C73.1 R29.2 R31.2 R32.2 R33.2 TP14.1 U24.5 | length 671
  Top Layer w30: R33.2@2232.09,2466.97 R31.2@2232.09,2571.97 ; R29.2@2232.09,2676.97 R29.2@2232.09,2675.97 R31.2@2232.09,2571.97 ; R31.2@2236.61,2576.5 R31.2@2232.09,2571.97 ; 2326.61,2576.5 R32.2@2605,2576.5 C73.1@2670,2576.5 2712.68,2576.5 U24.5@2761.14,2624.96
VCC: C32.1 C33.1 C34.1 C35.1 C46.1 C47.1 C48.1 C49.1 C52.1 C53.1 C56.1 D12.2 D13.2 D14.2 J7.1 R110.1 U2.5 U6.5 U8.5 U10.5 | length 7676.1
  Top Layer w20: U10.5@1838.27,5075 1849.5,5075 C48.1@1849.5,4995
  Top Layer w25: C48.1@1849.5,4995 1849.5,4916.5 C49.1@1851,4915 1851,4855 1866,4840 v1(2520,4840)
  Top Layer w30: R110.1@2764.83,-350.68 v1(2764.83,-270)
  PWR w60: v1(2520,4840) 2520,3920 2153,3553 v1(2153,3486) 2153,3443 2418,3178 2418,2522 2187,2291 2187,2083 2401,1869 2401,637 J7.1@2225,461 2225,364 2118,257 1920,257 1849,186 v1(1849,42) 1922,-31 2619,-31 2764.83,-176.83 v1(2764.83,-270)
  other v1: 1832,1794 1877,1794 2187,2156 1833,3029 1878,3029
VCC_UT: C21.2 C23.1 C26.1 C50.1 J6.1 R41.1 U5.5 U22.2 | length 293.6
  GND w30: 1923,832.32 2124,631.32 v1(2124,622)
  other v1: 1833,1169.97 1878,1169.97
VCC_VT: C40.1 C41.1 C54.1 J13.1 R42.1 U7.5
  other v1: 1833,2404.97 1878,2404.97
VCC_WT: C3.1 C4.1 C51.1 C71.2 J5.1 R43.1 U1.5 U20.2
  other v1: 1833,3643 1878,3643
VDC+: C111.1 C112.1 D9.1 D10.1 J3.2 J8.1 R45.1 R98.2 TP25.1 TP26.1 TP27.1 U24.16 U24.17 U24.18 U24.30 U24.31 U24.32 | length 619.5
  GND w50: TP25.1@4040,160 4150,160 ; TP26.1@4040,4384 4124,4384 4125,4385
  Bottom Layer w30: U24.16@4126.69,-75.24 4172.75,-121.29 D10.1@4172.75,-300.55 4172.75,-479.34 R98.2@4172.09,-480
VDC-: C12.1 C13.1 C28.1 C31.1 C32.2 C33.2 C34.2 C35.2 C43.1 C45.1 C46.2 C47.2 C48.2 C49.2 C64.1 C67.1 C75.2 C76.2 C77.2 C79.2 C82.1 C91.1 C94.1 C95.2 C96.2 C97.2 C111.2 C112.2 J7.2 R5.2 R10.2 R12.1 R22.2 R24.2 R26.1 R34.2 R36.2 R38.1 R51.1 R91.1 R107.1 R109.1 TP20.1 TP22.1 TP24.1 TP33.1 TP34.1 TP35.1 TP36.1 U9.2 U10.8 U12.4 U15.4 U23.1 U24.4 U24.8 U24.12 U24.13 U24.14 U24.15 U24.20 U24.33 U24.34 U24.35 XF1.1 XF1.2 | length 8400
  Top Layer w15: U10.8@1838.27,5225 1908.42,5225 1908.17,5225.25 v1(1906.35,5225.25) ; U15.4@1944.3,-260.55 2019.73,-260.55 v1(2039.73,-240.55) R91.1@2113.24,-240.55 ; U9.2@2324.29,-405 v1(2380,-405)
  Top Layer w20: C48.2@1912.5,4995 v1(1961,4995) v1@1963.01,4995 ; C49.2@1931,4915 v1(1991,4915) ; v1(1943.73,-646.55) 1944.3,-647.12 U12.4@1944.3,-688.55 ; C91.1@2106.23,-430.55 2106.23,-495.23 C67.1@2119,-508 v1(2119,-572) ; R107.1@2238,-682.99 C94.1@2303,-682.99 v1(2303,-749) ; v1(2301.5,-553) C79.2@2301.5,-490 ; TP36.1@2428,-219 2460,-187 3083,-187 3964,694 4986.87,694 U24.20@5042.64,749.76 ; v1(2508.33,-657.68) C95.2@2577.33,-657.68 ; v1(2577.33,-726.68) C95.2@2577.33,-657.68 ; C95.2@2591.47,-643.55 C95.2@2577.33,-657.68 ; U23.1@2739.73,-578.55 2739.73,-527.78 C97.2@2764.83,-502.68 ; C96.2@2787.33,-426.68 2787.33,-480.18 C97.2@2764.83,-502.68 ; v1(2795,-617) 2795,-532.86 C97.2@2764.83,-502.68
  Top Layer w30: C46.2@1923.5,1850 1959,1814.5 v1(1959,1794) ; C34.2@1924.5,97 1976.5,45 v1(2046,45) ; C32.2@1924.5,3085 1946,3063.5 v1(1946,3029) ; C82.1@2093.76,-835.95 2101,-843.18 C64.1@2101,-912 v1(2171,-912) ; v1(2305,5265) 2385,5265 2515,5395 3371,5395 XF1.2@3698,5722 ; R12.1@2601,700.5 C75.2@2670,700.5 2735.21,700.5 U24.12@2761.14,674.57 2800.71,635 TP20.1@2890,635 ; R38.1@2605,1913.5 C76.2@2670,1913.5 2722.2,1913.5 U24.8@2761.14,1874.57 2810.71,1825 TP22.1@2890,1825 ; R26.1@2605,3113.5 C77.2@2670,3113.5 2722.2,3113.5 U24.4@2761.14,3074.57 2800.71,3035 TP24.1@2890,3035
  GND w50: U24.4@2761.14,3050.86 U24.4@2761.14,3074.57 ; 3675,160 TP33.1@3770,160 ; 3698,4384 TP34.1@3770,4384
  GND w100: 2794,-515 C111.2@3358.66,-515
  Bottom Layer w30: C47.2@1933,1850 1960.12,1822.88 1960.12,1795.12 v1(1959,1794) ; C35.2@1934,97 1986,45 v1(2046,45) ; C33.2@1934,3085 1946,3073 v1(1946,3029) ; R109.1@3213,-516.01 3214.01,-515 C111.2@3358.66,-515
  other v1: 2037,2245 1992,2246 2038,3480 1993,3481
VDC-_F: C78.2 J8.2 Q1.3 R96.1 XF2.1 XF2.2 | length 385.8
  Top Layer w30: R96.1@5589,5718 C78.2@5654,5718 5654,5817 5738,5901 Q1.3@5841,5901
VEE: C52.2 C53.2 C56.2 J7.3 R101.1 R102.1 R105.1 | length 3398.2
  PWR w60: v1(2018,3413) v1(2062,3413) 2315,3160 2315,2583 2095,2363 2095,2012 2308,1799 2308,1009 2023,724 J7.3@2023,461
  other v1: 2095,2175
VEE_UT: C50.2 J6.3 R99.1
VEE_VT: C54.2 J13.3 R103.1
VEE_WT: C51.2 J5.3 R100.1
W_BOT: C77.1 R9.2 R11.2 R13.2 R26.2 TP23.1 U24.3 | length 674.7
  Top Layer w30: R13.2@2232.09,3085 R11.2@2232.09,3190 ; R9.2@2232.09,3295 R11.2@2232.09,3190 ; R11.2@2245.59,3176.5 R11.2@2232.09,3190 ; 2335.59,3176.5 R26.2@2605,3176.5 C77.1@2670,3176.5 2712.68,3176.5 U24.3@2761.14,3224.96
W_PHASE: J4.3 R86.1 R118.2 | length 4607.3
  Top Layer w15: R86.1@2161.23,4471.58 2174.23,4484.58 2538.43,4484.58 2743.85,4690 3093,4690 3164,4619 3164,4461 4605,3020 5416.43,3020 5492,3095.57 5492,3258 5534,3300 R118.2@5682.6,3300
  other v1: 5878.55,3078.55 5967.55,3079.55 5877.55,3167.55 5966.55,3168.55 5876.55,3256.55 5965.55,3257.55
W_PHASE_REF: R85.1 R118.1 TP28.1 TP29.1 U24.27 U24.28 U24.29 | length 4867.8
  Top Layer w15: R85.1@2161.23,4536.58 2183.23,4514.58 2526,4514.58 2733.42,4722 3105,4722 3195,4632 3195,4476 4621,3050 5404,3050 5462,3108 5462,3259 5421,3300 R118.1@5257.4,3300
  Top Layer w50: TP29.1@5257.4,3557.4 TP29.1@5260,3560
  GND w50: TP28.1@4755,3450 4755.24,3449.76 U24.29@5042.64,3449.76
W_TOP: C72.1 R3.2 R17.2 R19.2 R20.2 TP12.1 U24.1 | length 683
  Top Layer w30: R19.2@2232.09,3705 R17.2@2232.09,3810 ; R3.2@2232.09,3915 R17.2@2232.09,3810 ; 2285,3810 R17.2@2232.09,3810 ; 2375,3810 2408.5,3776.5 R20.2@2605,3776.5 C72.1@2670,3776.5 2712.68,3776.5 U24.1@2761.14,3824.96
pads on no net: FID1.1 FID2.1 FID3.1 FID4.1 FID5.1 FID6.1 H1.1 H2.1 H3.1 H4.1 H5.0 H6.0 H7.0 H8.0 J1.9 J1.11 J1.21 J1.26 J1.27 LBL1.0 U3.8 U4.1 U23.4 U23.5 U24.MH1 U24.MH2 U24.MH3 U24.MH4

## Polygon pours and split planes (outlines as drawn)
W_BOT on Top Layer "W_BOT_L01_P817" (solid, remove dead copper, pour order 817): 2204,3332 2204,3050 2211,3043 2349,3043 2394,3043 2497,3146 2504,3153 2577,3153 2908,3153 2943,3188 2943,3299 2905,3337 2355,3337 2209,3337
V_TOP on Top Layer "V_TOP_L01_P821" (solid, remove dead copper, pour order 821): 2205,2717 2205,2431 2222,2414 2420,2414 2543,2537 2557,2551 2616,2551 2880,2551 2932,2603 2932,2675 2933,2676 2933,2697 2892,2738 2226,2738
V_BOT on Top Layer "V_BOT_L01_P823" (solid, remove dead copper, pour order 823): 18 vertices, not listed, extent 2204,1799 2940,2120
U_TOP on Top Layer "U_TOP_L01_P825" (solid, remove dead copper, pour order 825): 2205,1480 2205,1193 2219,1179 2330,1179 2379,1179 2550,1350 2596,1350 2879,1350 2931,1402 2937,1408 2937,1460 2937,1480 2909,1508 2396,1508 2233,1508
W_TOP on Top Layer "W_TOP_L01_P819" (solid, remove dead copper, pour order 819): 2204,3951 2204,3670 2215,3659 2439,3659 2526,3746 2532,3752 2590,3752 2896,3752 2939,3795 2939,3921 2893,3967 2220,3967
GND_UT on Top Layer "Top Layer-MU" (solid, remove dead copper, pour order 852): 21 vertices, not listed, extent 1900,1481.97 2158,1651.97
GND_VT on Top Layer "Top Layer-MU" (solid, remove dead copper, pour order 571): 21 vertices, not listed, extent 1900,2720.97 2158,2890.97
GND_WT on Top Layer "GND_WT_L01_P850" (solid, remove dead copper, pour order 850): 29 vertices, not listed, extent 1906,3959 2248,4332
U_PHASE_REF on Top Layer "Top Layer-MU" (solid, remove dead copper, pour order 777): 5342,1794 5024,1794 4990,1760 4990,1320 5010,1300 5350,1300 5365,1315 5365,1771
U_PHASE on Top Layer "Top Layer-MU" (solid, remove dead copper, pour order 755): 5576,1322 5576,1681 5957,2062 6165,2062 6195,2032 6195,1710 5789,1304 5594,1304
W_PHASE on Top Layer "Top Layer-MU" (solid, remove dead copper, pour order 731): 5576,3475 5576,3109 5957,2728 6165,2728 6195,2758 6195,3080 5789,3486 5587,3486
GND_UT on Top Layer "Top Layer-MU" (solid, remove dead copper, pour order 641): 2184.77,780.55 2184.77,645.55 2189.77,640.55 2284.77,640.55 2289.77,645.55 2289.77,780.55 2284.77,785.55 2189.77,785.55 2184.77,780.55
VCC_UT on Top Layer "Top Layer-MU" (solid, remove dead copper, pour order 639): 2104.77,740.55 2104.77,605.55 2109.77,600.55 2159.77,600.55 2164.77,605.55 2164.77,735.55 2159.77,740.55
GND_UT on Top Layer "Top Layer-MU" (solid, remove dead copper, pour order 637): 1926.77,762.55 1920.77,756.55 1920.77,664.55 1925.77,659.55 2065.77,659.55 2071.77,665.55 2071.77,751.55 2060.77,762.55 1995.77,762.55
NetC85_2 on Top Layer "Top Layer-MU" (solid, remove dead copper, pour order 635): 2159.77,785.55 1919.77,785.55 1909.77,795.55 1904.77,800.55 1904.77,885.55 1909.77,890.55 1979.77,890.55 2014.77,855.55 2154.77,855.55 2164.77,845.55 2164.77,790.55 2159.77,785.55
NetC7_1 on Top Layer "NETC7_1_L01_P421" (solid, remove dead copper, pour order 421): 20 vertices, not listed, extent 552,3099 724,3440
GND on Top Layer "GND_L01_P419" (solid, remove dead copper, pour order 419): 523,3360 523,3434 517,3440 422,3440 413,3431 413,3055 425,3043 507,3043 515,3051 523,3059 523,3359
GND on Top Layer "GND_L01_P417" (solid, remove dead copper, pour order 417): 523,1610 523,1536 517,1530 422,1530 413,1539 413,1915 425,1927 507,1927 515,1919 523,1911 523,1611
NetC1_2 on Top Layer "NETC1_2_L01_P415" (solid, remove dead copper, pour order 415): 20 vertices, not listed, extent 552,1530 724,1871
3V3 on Top Layer "3V3_L01_P181" (solid, remove dead copper, pour order 181): 557,4150 557,4435 572,4450 577,4455 607,4455 828,4455 839,4444 839,4055 819,4035 567,4035 557,4045
GND on Top Layer "GND_L01_P179" (solid, remove dead copper, pour order 179): 542,4175 532,4165 62,4165 47,4180 47,4320 57,4330 337,4330 352,4345 352,4440 367,4455 532,4455 542,4445
5V0 on Top Layer "5V0_L01_P177" (solid, remove dead copper, pour order 177): 532,4145 252,4145 237,4130 237,3910 247,3900 532,3900 542,3910 542,4140 537,4145
NetD1_2 on Top Layer "NETD1_2_L01_P175" (solid, remove dead copper, pour order 175): 57,4140 167,4140 177,4130 177,3915 177,3905 172,3900 57,3900 47,3910 47,4130
NetC15_2 on Top Layer "Top Layer-MU" (solid, remove dead copper, pour order 527): 1895,3910 1820,3910 1815,3915 1815,4130 1825,4140 1875,4140 1880,4135 1880,3990 1895,3975 1900,3970 1915,3955 1932,3938 1998,3938 1998,3901 1904,3901
VCC_WT on Top Layer "Top Layer-MU" (solid, remove dead copper, pour order 539): 1817,3786 1817,3628 1823,3622 1896,3622 1900,3626 1900,3649 1883,3666 1883,3743 1895,3755 1895,3782.07 1887.07,3790 1821,3790
NetC12_2 on Top Layer "Top Layer-MU" (solid, remove dead copper, pour order 549): 1895,3290 1820,3290 1815,3295 1815,3495 1820,3500 1875,3500 1880,3495 1880,3365 1927,3318 1998,3318 1998,3281 1904,3281
VCC on Top Layer "Top Layer-MU" (solid, remove dead copper, pour order 553): 1817,3166 1817,3015 1821,3011 1895,3011 1900,3016 1900,3035 1883,3052 1883,3123 1895,3135 1895,3162.07 1887.07,3170 1821,3170
NetC80_2 on Top Layer "Top Layer-MU" (solid, remove dead copper, pour order 561): 1980,4445 1910,4445 1905,4440 1905,4350 1915,4340 2140,4340 2145,4345 2145,4410 2135,4420 2005,4420
VCC_WT on Top Layer "Top Layer-MU" (solid, remove dead copper, pour order 565): 19 vertices, not listed, extent 1993,4060 2149,4292
VCC_VT on Top Layer "Top Layer-MU" (solid, remove dead copper, pour order 569): 1817,2547.97 1817,2389.97 1823,2383.97 1896,2383.97 1900,2387.97 1900,2410.97 1883,2427.97 1883,2504.97 1895,2516.97 1895,2544.04 1887.07,2551.97 1821,2551.97
NetC37_2 on Top Layer "Top Layer-MU" (solid, remove dead copper, pour order 573): 1895,2671.97 1820,2671.97 1815,2676.97 1815,2886.97 1819,2890.97 1876,2890.97 1880,2886.97 1880,2751.97 1895,2736.97 1900,2731.97 1915,2716.97 1932,2699.97 1998,2699.97 1998,2662.97 1904,2662.97
VCC on Top Layer "Top Layer-MU" (solid, remove dead copper, pour order 587): 1816,1931 1816,1780 1820,1776 1894,1776 1899,1781 1899,1800 1882,1817 1882,1888 1894,1900 1894,1927.07 1886.07,1935 1820,1935
NetC43_2 on Top Layer "Top Layer-MU" (solid, remove dead copper, pour order 589): 1894,2055 1819,2055 1814,2060 1814,2260 1819,2265 1874,2265 1879,2260 1879,2130 1926,2083 1997,2083 1997,2046 1903,2046
NetC28_2 on Top Layer "Top Layer-MU" (solid, remove dead copper, pour order 597): 1895,302 1820,302 1815,307 1815,507 1820,512 1875,512 1880,507 1880,377 1927,330 1998,330 1998,293 1904,293
VCC on Top Layer "Top Layer-MU" (solid, remove dead copper, pour order 599): 1817,178 1817,27 1821,23 1895,23 1900,28 1900,47 1883,64 1883,135 1895,147 1895,174.07 1887.07,182 1821,182
NetC18_2 on Top Layer "Top Layer-MU" (solid, remove dead copper, pour order 603): 1895,1436.97 1820,1436.97 1815,1441.97 1815,1651.97 1819,1655.97 1876,1655.97 1880,1651.97 1880,1516.97 1895,1501.97 1900,1496.97 1915,1481.97 1932,1464.97 1998,1464.97 1998,1427.97 1904,1427.97
VCC_UT on Top Layer "Top Layer-MU" (solid, remove dead copper, pour order 607): 1817,1312.97 1817,1154.97 1823,1148.97 1896,1148.97 1900,1152.97 1900,1175.97 1883,1192.97 1883,1269.97 1895,1281.97 1895,1309.04 1887.07,1316.97 1821,1316.97
VDC- on Top Layer "Top Layer-MU" (solid, remove dead copper, pour order 623): 29 vertices, not listed, extent 1903,351 2159,518
VDC- on Top Layer "Top Layer-MU" (solid, remove dead copper, pour order 631): 17 vertices, not listed, extent 1901,2107 2080,2266
VDC- on Top Layer "Top Layer-MU" (solid, remove dead copper, pour order 633): 17 vertices, not listed, extent 1902,3342 2081,3501
W_PHASE_REF on Top Layer "Top Layer-MU" (solid, remove dead copper, pour order 689): 5346,3594 5010,3594 4990,3574 4990,3120 5010,3100 5350,3100 5365,3115 5365,3575
NETJ1_26 on Top Layer "NETJ1_26_L01_P799" (solid, remove dead copper, pour order 799): 303,1573 303,1274 295,1266 113,1266 102,1277 102,1637 121,1656 293,1656 303,1646
GND on Top Layer "Top Layer-MU" (solid, remove dead copper, pour order 801): 357,1393 357,1455 364,1462 488,1462 496,1454 496,1274 488,1266 364,1266 357,1273
NetJ4_2 on Top Layer "NETJ4_2_L01_P803" (solid, remove dead copper, pour order 803): 18 vertices, not listed, extent 4989,2199 6205,2614
NetD9_2 on Top Layer "Top Layer-MU" (solid, remove dead copper, pour order 884): 17 vertices, not listed, extent 5483,4214 6157,5298
U_BOT on Top Layer "U_BOT_L01_P872" (solid, remove dead copper, pour order 872): 23 vertices, not listed, extent 2204,42 2941,910
GND on Top Layer "Top Layer-MU" (solid, remove dead copper, pour order 948): 17 vertices, not listed, extent 22.97,-963.76 1641.97,5998.24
